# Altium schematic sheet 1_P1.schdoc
size 307 x 218 mm; Symbol: Drawing-Symbol_A4; Device: Drawing-Symbol_A4; @Project Name: sonos_knobs; @Page Count: 2; @Update Date: 2025-01-27; @Create Date: 2025-01-11; @Schematic Name: Schematic1; @Page No: 1; @Page Name: P1; Company: EasyEDA.com; Version: V1.0; Page Size: A4; @Create Time: 19:53:40; @Update Time: 17:45:01; Width: 1170; Height: 825; Region Start: 1; X Region Count: 6; Y Region Count: 4; Blade Width: 10; Title Block Position: 3; @Board Name: Board1
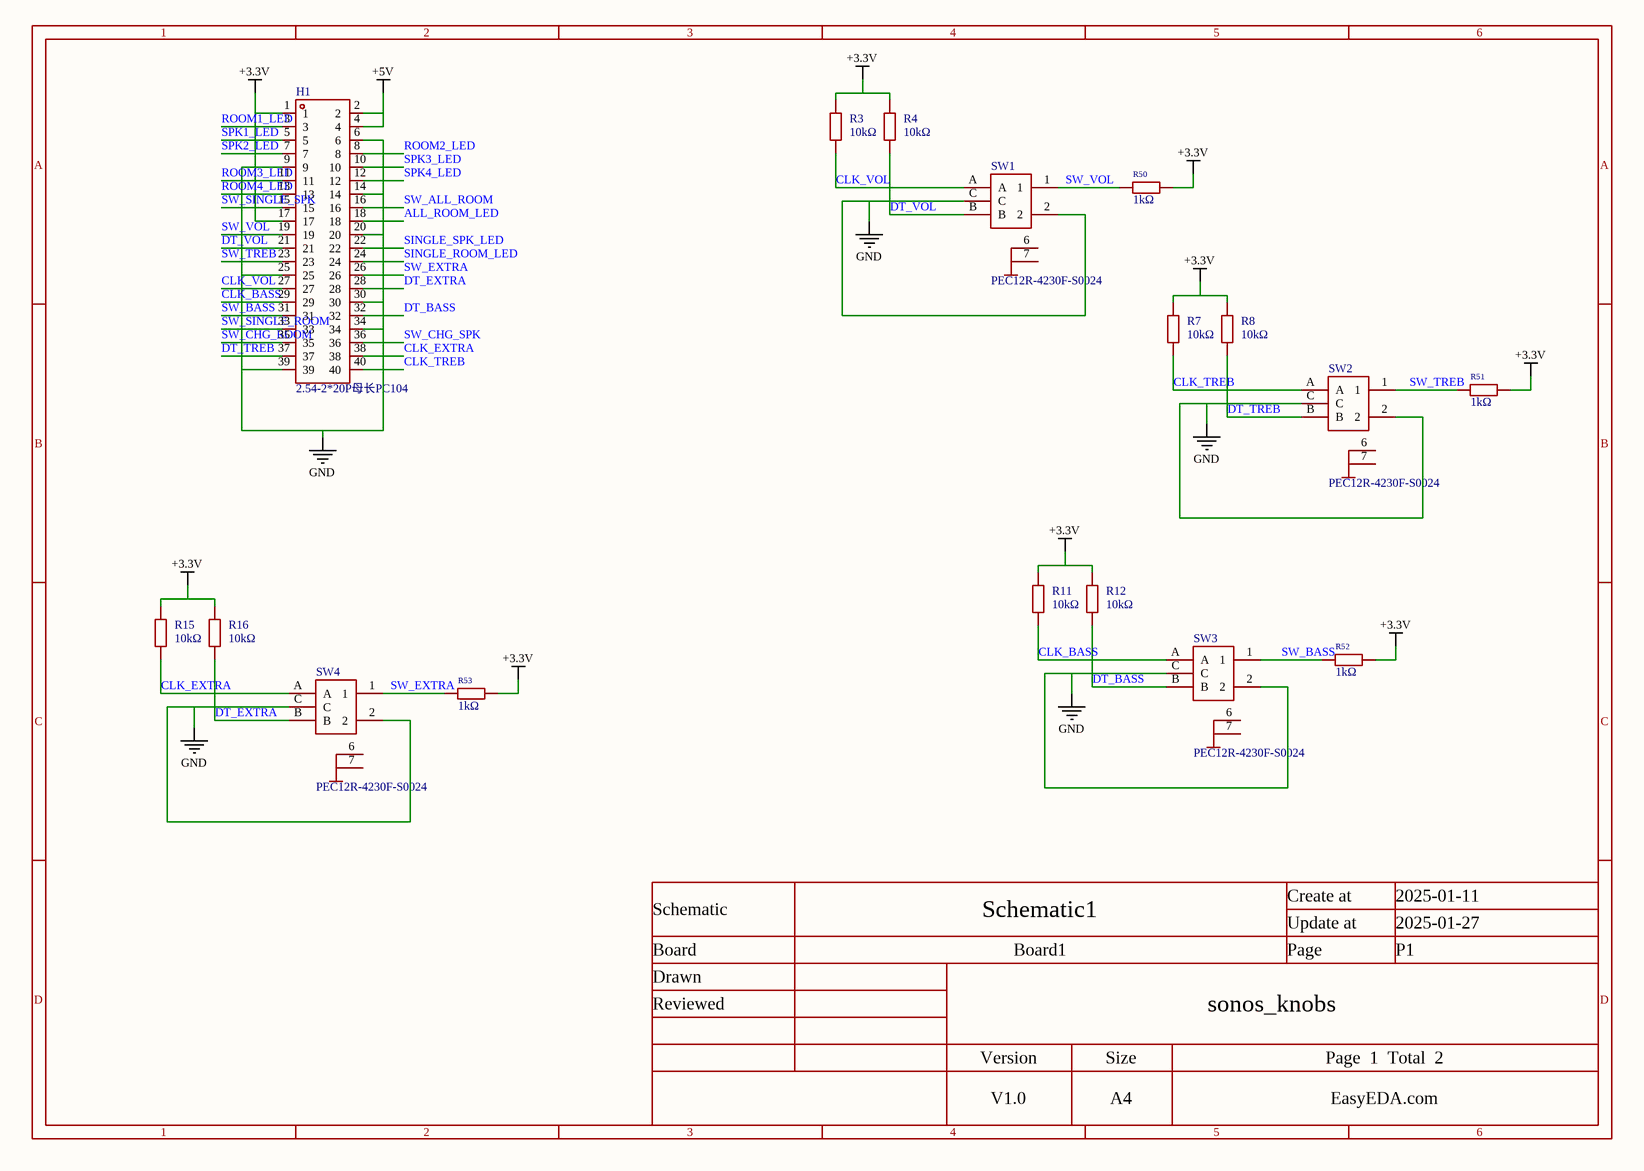
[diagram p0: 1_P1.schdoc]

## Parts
H1  2.54-2*20P母长PC104  [HDR-TH_40P-P2.54-V-F-R2-C20-S2.54-2]
R3  10kΩ  [C0402]
R4  10kΩ  [C0402]
R7  10kΩ  [C0402]
R8  10kΩ  [C0402]
R11  10kΩ  [C0402]
R12  10kΩ  [C0402]
R15  10kΩ  [C0402]
R16  10kΩ  [C0402]
R50  1kΩ  [C0402]
R51  1kΩ  [C0402]
R52  1kΩ  [C0402]
R53  1kΩ  [C0402]
SW1  PEC12R-4230F-S0024  [SW-TH_PEC12R-4230F-S0024]
SW2  PEC12R-4230F-S0024  [SW-TH_PEC12R-4230F-S0024]
SW3  PEC12R-4230F-S0024  [SW-TH_PEC12R-4230F-S0024]
SW4  PEC12R-4230F-S0024  [SW-TH_PEC12R-4230F-S0024]

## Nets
+3.3V: H1.1 H1.17 R3.1 R4.1 R7.2 R8.2 R11.1 R12.1 R15.2 R16.2 R50.2 R51.2 R52.2 R53.2
+5V: H1.2 H1.4
GND: H1.6 H1.9 H1.14 H1.20 H1.25 H1.30 H1.34 H1.39 SW1.2 SW1.C SW2.2 SW2.C SW3.2 SW3.C SW4.2 SW4.C
ALL_ROOM_LED: H1.18
CLK_BASS: H1.29 R11.2 SW3.A
CLK_EXTRA: H1.38 R15.1 SW4.A
CLK_TREB: H1.40 R7.1 SW2.A
CLK_VOL: H1.27 R3.2 SW1.A
DT_BASS: H1.32 R12.2 SW3.B
DT_EXTRA: H1.28 R16.1 SW4.B
DT_TREB: H1.37 R8.1 SW2.B
DT_VOL: H1.21 R4.2 SW1.B
ROOM1_LED: H1.3
ROOM2_LED: H1.8
ROOM3_LED: H1.11
ROOM4_LED: H1.13
SINGLE_ROOM_LED: H1.24
SINGLE_SPK_LED: H1.22
SPK1_LED: H1.5
SPK2_LED: H1.7
SPK3_LED: H1.10
SPK4_LED: H1.12
SW_ALL_ROOM: H1.16
SW_BASS: H1.31 R52.1 SW3.1
SW_CHG_ROOM: H1.35
SW_CHG_SPK: H1.36
SW_EXTRA: H1.26 R53.1 SW4.1
SW_SINGLE_ROOM: H1.33
SW_SINGLE_SPK: H1.15
SW_TREB: H1.23 R51.1 SW2.1
SW_VOL: H1.19 R50.1 SW1.1

Not connected (* = marked no-connect by the designer): SW1 6 7; SW2 6 7; SW3 6 7; SW4 6 7

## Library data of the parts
H1 = 2.54-2*20P母长PC104: Manufacturer: BOOMELE(博穆精密); Symbol: 2.54mm 2*20P; Add into BOM: yes; Holes Structure: 2x20P; Pitch: 2.54mm; Number of Holes: 40P
R3 R4 R7 R8 R11 R12 R15 R16 = 0402WGF1002TCE: Manufacturer: UNI-ROYAL(厚声); Add into BOM: yes; Tolerance: ±1%; Temperature Coefficient: ±100ppm/℃
R50-R53 = 0402WGF1001TCE: Manufacturer: UNI-ROYAL(厚声); Add into BOM: yes; Tolerance: ±1%; Temperature Coefficient: ±100ppm/℃
SW1-SW4 = PEC12R-4230F-S0024: Manufacturer: BOURNS; Add into BOM: yes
